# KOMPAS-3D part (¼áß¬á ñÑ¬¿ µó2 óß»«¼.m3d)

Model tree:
1. Эскиз:1
2. Операция выдавливания:1
     Толщина стенки 1 = 7; Толщина стенки 2 = 6; Расстояние 1 = 0.6
3. Эскиз:2
4. Вырезать элемент выдавливания:1
     Толщина стенки 2 = 15; Расстояние 1 = 10
5. Эскиз:3
6. Вырезать элемент выдавливания:2
     Толщина стенки 1 = 8; Толщина стенки 2 = 15; Расстояние 1 = 10
7. Эскиз:4
8. Вырезать элемент выдавливания:3
     Толщина стенки 1 = 7; Расстояние 1 = 10
